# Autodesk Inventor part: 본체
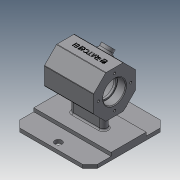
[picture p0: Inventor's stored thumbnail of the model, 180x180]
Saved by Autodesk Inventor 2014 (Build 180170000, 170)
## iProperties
Created: 2018-06
Part Number: 본체
Material: 일반
Document SubType Name: Modeling
Designer: NET
Density: 1 g/cm^3
Appearance: 기본값
Author: NET
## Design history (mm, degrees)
sketch "스케치1"
  geometry: L1 (-55, -55)-(55, -55); L2 (55, -55)-(55, 55); L3 (55, 55)-(-55, 55); L4 (-55, 55)-(-55, -55); L5 (-55, -55)-(55, 55); L6 (55, -55)-(-55, 55); 1 further point
  constraints: 12 end point, 2 midpoint, 2 parallel, 2 perpendicular, 1 horizontal
  dimensions: "d0" = 110 distance of L2.end L3.end
extrude "돌출1" new body sketch "스케치1" distance "d1" = 5; taper "d2" = 0 deg
sketch "스케치2"
  geometry: L1 (55, -55)-(55, 55) reference; L2 (55, 55)-(-55, 55) reference; L3 (-55, -25)-(55, -25); L4 (55, -25)-(55, 25); L5 (55, 25)-(-55, 25); L6 (-55, 25)-(-55, -25); L7 (-55, -25)-(55, 25); L8 (55, -25)-(-55, 25); 1 further point
  constraints: 12 end point, 2 midpoint, 2 parallel, 1 horizontal, 1 perpendicular, 1 point on line
  dimensions: "d3" = 30 distance between parallel lines of L2 L5
extrude "돌출2" join sketch "스케치2" distance "d4" = 5; taper "d5" = 0 deg
sketch "스케치3" dims "d6" = 60
  geometry: L1 (12.426, 92)-(30, 74.426); L2 (30, 74.426)-(30, 49.574); L3 (30, 49.574)-(12.426, 32); L4 (12.426, 32)-(-12.426, 32); L5 (-12.426, 32)-(-30, 49.574); L6 (-30, 49.574)-(-30, 74.426); L7 (-30, 74.426)-(-12.426, 92); L8 (-12.426, 92)-(12.426, 92); 4 further points
  constraints: 16 end point, 3 vertical alignment, 1 coincident, 1 midpoint, 19 other
  dimensions: "d7" = 62 distance of point (0, 0) point (0, 62)
extrude "돌출3" join sketch "스케치3" stored distance "d8" = 70; taper "d9" = 0 deg
sketch "스케치4"
  geometry: L1 (55, 25)-(-55, 25) reference; L2 (-19, 0)-(19, 0); L3 (-19, -5)-(19, -5); L4 (19, 5)-(-19, 5); A1 r 5 centre (-19, 0) between (-19, 5) and (-19, -5); A2 r 5 centre (19, 0) between (19, -5) and (19, 5); 1 further point
  constraints: 8 end point, 4 point on circle, 4 tangent, 2 centre point, 2 parallel, 1 horizontal alignment, 1 midpoint
  dimensions: "d10" = 5 radius of A2; "d11" = 38 distance of L2.start L2.end
extrude "돌출4" join sketch "스케치4" stored distance "d12" = 70; taper "d13" = 0 deg
sketch "스케치5"
  geometry: L1 (12.426, 92)-(30, 74.426) reference; L2 (30, 74.426)-(30, 49.574) reference; L3 (30, 49.574)-(12.426, 32) reference; L4 (12.426, 32)-(-12.426, 32) reference; L5 (-12.426, 32)-(-30, 49.574) reference; L6 (-30, 49.574)-(-30, 74.426) reference; L7 (-30, 74.426)-(-12.426, 92) reference; L8 (-12.426, 92)-(12.426, 92) reference; L9 (0, 62)-(26.163, 88.163); L10 (0, 62)-(30, 62); 2 further points
  constraints: 4 end point, 2 midpoint, 1 horizontal alignment, 1 perpendicular, 1 vertical alignment
  dimensions: "d14" = 45 deg angle of L9 L10; "d15" = 7 distance from line of L9.end L1
  node "투영된 루프1"
node "작업 평면1"
sketch "스케치6"
  geometry: C1 r 8 at (0, 0); 4 further points
  constraints: 1 centre point, 1 coincident
  dimensions: "d16" = 16 diameter of C1
extrude "돌출5" join sketch "스케치6" stored distance "d17" = 70; taper "d18" = 0 deg
sketch "스케치7"
  geometry: L1 (-35, 74.426)-(-35, 49.574) reference; L2 (-35, 92)-(-35, 74.426) reference; L3 (-35, 49.574)-(-35, 32) reference; L4 (35, 74.426)-(35, 92) reference; L5 (35, 49.574)-(35, 74.426) reference; L6 (35, 32)-(35, 49.574) reference; L7 (-52.18, 62)-(53.63, 62); L8 (55, 0)-(-55, 0) reference; L9 (-35, 78)-(-23.3, 78); L10 (-23, 77.7)-(-23, 76); L11 (-23, 76)-(-20, 76); L12 (-20, 76)-(-20, 84); L13 (-17, 87)-(17, 87); L14 (20, 84)-(20, 76); L15 (20, 76)-(23, 76); L16 (23, 76)-(23, 77.7); L17 (23.3, 78)-(35, 78); L18 (-35, 78)-(-35, 62); L19 (35, 78)-(35, 62); L20 (35, 62)-(-35, 62); A1 r 0.3 centre (-23.3, 77.7) between (-23, 77.7) and (-23.3, 78); A2 r 0.3 centre (23.3, 77.7) between (23.3, 78) and (23, 77.7); A3 r 3 centre (17, 84) between (20, 84) and (17, 87); A4 r 3 centre (-17, 84) between (-17, 87) and (-20, 84); 4 further points
  constraints: 26 end point, 10 point on line, 8 point on circle, 8 tangent, 7 parallel, 5 collinear, 4 centre point, 3 perpendicular, 2 equal radius, 2 midpoint
  dimensions: "d19" = 62 distance between parallel lines of L8 L7; "d20" = 40 distance of point (-20, 87) point (20, 87); "d21" = 12 distance of point (23, 78) L17.end; "d22" = 50 diameter of L13 L7; "d23" = 32 diameter of L9 L7; "d24" = 28 diameter of L11 L7; "d25" = 0.3 radius of A1; "d26" = 3 radius of A3
revolve "회전1" sketch "스케치7" stored, may be unused: angle "d27" = 90 deg
chamfer "모따기1" distance "d28" = 1; stored, may be unused: second distance "d29" = 2, angle "d30" = 45 deg
sketch "스케치8"
  geometry: C1 r 17 at (-62, 0) reference; 2 further points
  constraints: 1 vertical alignment
  dimensions: "d31" = 23 distance of C1.centre point (-62, 23)
hole "구멍1" sketch "스케치8" at (-62, 23) diameter "d32" = 3.242; stored, may be unused: countersink angle "d36" = 90 deg, drill point angle "d38" = 118 deg; dims "d33" = 8, "d34" = 4, "d35" = 2, "d37" = 10
sketch "스케치9"
  geometry: C1 r 8 at (0, 0) reference; C2 r 4 at (0, 0); 1 further point
  constraints: 1 centre point, 1 coincident
  dimensions: "d42" = 8 diameter of C2
extrude "돌출6" cut sketch "스케치9" distance "d43" = 27.5; taper "d44" = 0 deg
chamfer "모따기2" distance "d45" = 1; stored, may be unused: second distance "d46" = 2, angle "d47" = 45 deg
sketch "스케치10"
  geometry: L1 (0, 24.853)-(0, 42.426) reference; L2 (70, 42.426)-(0, 42.426) reference; 2 further points
  constraints: 1 other
  dimensions: "d48" = 35 distance from line of L1 point (35, 12.426); "d49" = 30 distance from line of point (35, 12.426) L2
feature "엠보싱1" sketch "스케치10" dims "d0" = 110, "d6" = 60, "d7" = 62, "d50" = 0.5, "d51" = 0
sketch "스케치11"
  geometry: L1 (55, 55)-(-55, 55) reference; C1 r 5 at (0, 45); 1 further point
  constraints: 1 centre point
  dimensions: "d52" = 10 diameter of C1; "d53" = 10 distance from line of L1 C1.centre
extrude "돌출7" cut sketch "스케치11" distance "d54" = 27.5; taper "d55" = 0 deg
fillet "모깎기1" dims "d56" = 2
fillet "모깎기2" dims "d57" = 1
fillet "모깎기3" dims "d58" = 1
chamfer "모따기3" distance "d59" = 10; stored, may be unused: second distance "d60" = 2, angle "d61" = 45 deg
fillet "모깎기4" dims "d62" = 3
node "솔리드1"
pattern_circular "원형 패턴1" dims angle "d40" = 360 deg
mirror "대칭1"
mirror "대칭2"
